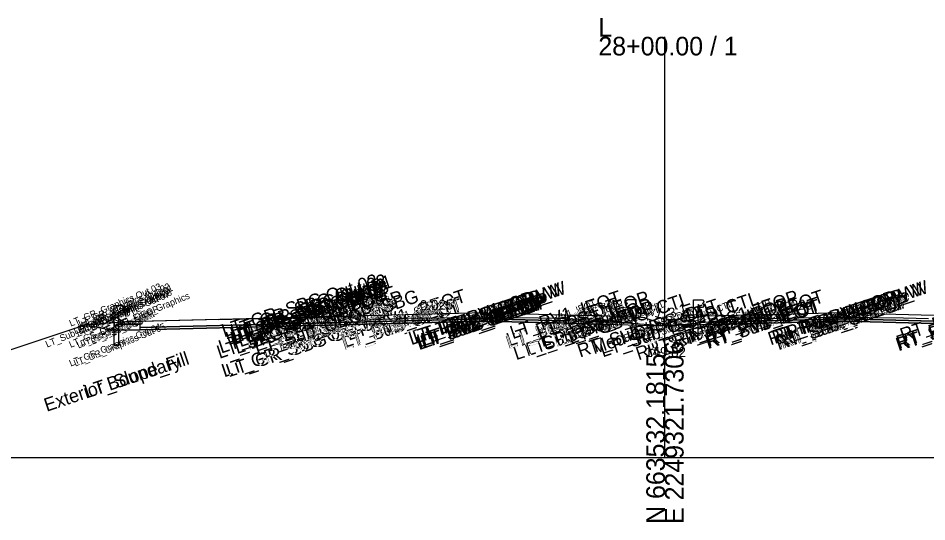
# Model space of a CAD drawing. Extents: x -26 to 2603, y -10 to 9566.
# Drawn here: x 1202.9 to 1339.3, y 7990.3 to 8066 of the extents above; entities that cross this region are included whole.
import ezdxf

# ---------------------------------------------------------------- set-up
doc = ezdxf.new("R2010")
doc.units = 0
for name, color, linetype in [('Exist Cross Section Cell', 7, 'Continuous'), ('Exist XS Center Line Elevation Label', 7, 'Continuous'), ('Exist XS Ground Line', 7, 'Continuous'), ('Matchline', 7, 'Continuous'), ('Prop CMT Concrete Structures', 7, 'Continuous'), ('Prop CMT Guardrail Graphics', 7, 'Continuous'), ('Prop CMT Pvmt Course 1', 7, 'Continuous'), ('Prop CMT Pvmt Course 2', 7, 'Continuous'), ('Prop CMT Pvmt Course 3', 7, 'Continuous'), ('Prop CMT Pvmt Course SBG', 7, 'Continuous'), ('Prop CMT Pvmt Surface', 7, 'Continuous'), ('Prop CMT Pvmt Surface Shoulder', 7, 'Continuous'), ('Prop CMT Shld Paved Course 1', 7, 'Continuous'), ('Prop CMT Shld Paved Course 2', 7, 'Continuous'), ('Prop CMT Shld Paved Course 3', 7, 'Continuous'), ('Prop CMT Slope Grass', 7, 'Continuous'), ('Prop CMT Subgrade Earthwork', 7, 'Continuous'), ('Prop XS SE Text', 7, 'Continuous'), ('Prop XS Side Slope Text', 7, 'Continuous'), ('Scratch_Level_9', 7, 'Continuous')]:
    doc.layers.add(name, color=color, linetype=linetype)

msp = doc.modelspace()

# ---------------------------------------------------------------- linework, layer by layer
at = {"layer": 'Exist Cross Section Cell'}
for p, q in [((1300, 8000), (1300, 8063.21)), ((1000, 8000), (1300, 8000)), ((1300, 8000), (1600, 8000))]:
    msp.add_line(p, q, dxfattribs=at)
at = {"layer": 'Exist XS Ground Line'}
for p, q in [((1261.36, 8020.9), (1272.58, 8021.03)), ((1272.58, 8021.03), (1281.01, 8020.95)), ((1281.01, 8020.95), (1283.78, 8020.91)), ((1314.57, 8020.89), (1325.58, 8021.07)), ((1325.58, 8021.07), (1335.79, 8020.96)), ((1335.79, 8020.96), (1337.73, 8020.94)), ((1337.73, 8020.94), (1339.59, 8020.85)), ((1254.47, 8020.61), (1254.61, 8020.62)), ((1254.61, 8020.62), (1257.59, 8020.75)), ((1257.59, 8020.75), (1259.01, 8020.81)), ((1259.01, 8020.81), (1260.76, 8020.9)), ((1260.76, 8020.9), (1261.36, 8020.9)), ((1283.78, 8020.91), (1284.6, 8020.87)), ((1284.6, 8020.87), (1286.97, 8020.77)), ((1286.97, 8020.77), (1290.29, 8020.53)), ((1290.29, 8020.53), (1298.19, 8019.93)), ((1298.19, 8019.93), (1300, 8019.82)), ((1300, 8019.82), (1300.63, 8019.78)), ((1300.63, 8019.78), (1309.9, 8020.7)), ((1309.9, 8020.7), (1311.47, 8020.83)), ((1311.47, 8020.83), (1314.57, 8020.89))]:
    msp.add_line(p, q, dxfattribs=at)
for points in [[(1233, 8020.72), (1245, 8021.02)], [(1245, 8021.02), (1251, 8021.17)], [(1251, 8021.17), (1253, 8021.1)], [(1253, 8021.1), (1254.47, 8020.61)], [(1213.05, 8019.9), (1157.74, 8001.46)], [(1216.05, 8020.14), (1213.05, 8019.9)], [(1219, 8020.37), (1216.05, 8020.14)], [(1221, 8020.42), (1219, 8020.37)], [(1233, 8020.72), (1221, 8020.42)]]:
    msp.add_lwpolyline(points, dxfattribs=at)
at = {"layer": 'Matchline'}
msp.add_lwpolyline([(1221.24, 8020.43), (1218.91, 8020.33), (1218.24, 8020.68)], dxfattribs=at)
msp.add_lwpolyline([(1221.24, 8020.43), (1218.91, 8020.33), (1218.24, 8020.68)], dxfattribs=at)
at = {"layer": 'Prop CMT Concrete Structures'}
for points in [[(1221.24, 8020.43), (1218.91, 8020.33), (1218.24, 8020.68)], [(1218.24, 8020.68), (1218.24, 8020.01)], [(1221.24, 8020.43), (1218.91, 8020.33), (1218.24, 8020.68)], [(1218.24, 8020.68), (1218.24, 8020.01)], [(1218.24, 8020.01), (1221.24, 8020.01)], [(1218.24, 8020.01), (1221.24, 8020.01)], [(1221.24, 8020.01), (1221.24, 8020.43)], [(1221.24, 8020.01), (1221.24, 8020.43)], [(1273, 8020.47), (1261, 8020.17)], [(1261, 8020.16), (1273, 8020.46)], [(1261, 8020.17), (1261, 8020.16)], [(1273, 8020.47), (1285, 8020.17)], [(1273, 8020.46), (1273, 8020.47)], [(1285, 8020.16), (1273, 8020.46)], [(1285, 8020.17), (1285, 8020.16)], [(1327, 8020.47), (1315, 8020.17)], [(1315, 8020.16), (1327, 8020.46)], [(1315, 8020.17), (1315, 8020.16)], [(1327, 8020.46), (1327, 8020.47)], [(1327, 8020.47), (1344.2, 8020.04)], [(1344.2, 8020.03), (1327, 8020.46)]]:
    msp.add_lwpolyline(points, dxfattribs=at)
at = {"layer": 'Prop CMT Guardrail Graphics'}
for points in [[(1295.7, 8023.69), (1294.37, 8023.69), (1294.1, 8023.4)], [(1295.7, 8023.69), (1294.37, 8023.69), (1294.1, 8023.4)], [(1295.7, 8017.69), (1295.7, 8023.69)], [(1304.3, 8023.69), (1305.63, 8023.69), (1305.9, 8023.4)], [(1304.3, 8023.69), (1305.63, 8023.69), (1305.9, 8023.4)], [(1304.3, 8017.69), (1304.3, 8023.69)], [(1294.1, 8023.4), (1294.37, 8023.11)], [(1294.1, 8023.4), (1294.37, 8023.11)], [(1294.37, 8023.11), (1294.1, 8022.82)], [(1294.37, 8023.11), (1294.1, 8022.82)], [(1294.1, 8022.82), (1294.37, 8022.53), (1295.04, 8022.53)], [(1294.1, 8022.82), (1294.37, 8022.53), (1295.04, 8022.53)], [(1295.04, 8022.53), (1295.04, 8017.69)], [(1305.9, 8022.82), (1305.63, 8022.53), (1304.96, 8022.53)], [(1305.9, 8022.82), (1305.63, 8022.53), (1304.96, 8022.53)], [(1304.96, 8022.53), (1304.96, 8017.69)], [(1305.9, 8023.4), (1305.63, 8023.11)], [(1305.9, 8023.4), (1305.63, 8023.11)], [(1305.63, 8023.11), (1305.9, 8022.82)], [(1305.63, 8023.11), (1305.9, 8022.82)], [(1261, 8020.17), (1221.24, 8019.18)], [(1221.24, 8019.17), (1261, 8020.16)], [(1261, 8020.16), (1261, 8020.17)], [(1285, 8020.17), (1285, 8020.16)], [(1290.79, 8020.02), (1290.78, 8020.03), (1290.28, 8020.04), (1285, 8020.17)], [(1285, 8020.16), (1290.79, 8020.02)], [(1309.21, 8020.02), (1309.22, 8020.03), (1309.72, 8020.04), (1315, 8020.17)], [(1315, 8020.16), (1309.21, 8020.02)], [(1315, 8020.17), (1315, 8020.16)]]:
    msp.add_lwpolyline(points, dxfattribs=at)
at = {"layer": 'Prop CMT Pvmt Course 1'}
for points in [[(1273, 8021.72), (1261, 8021.42)], [(1327, 8021.72), (1344.2, 8021.29)]]:
    msp.add_lwpolyline(points, dxfattribs=at)
at = {"layer": 'Prop CMT Pvmt Course 2'}
for p, q in [((1217.47, 8021.07), (1215.91, 8020.09)), ((1218.24, 8020.68), (1217.47, 8021.07)), ((1297, 8020.96), (1294, 8021.2)), ((1297, 8020.96), (1300, 8019.97)), ((1303, 8020.96), (1300, 8019.97)), ((1303, 8020.96), (1306, 8021.2)), ((1215.91, 8020.09), (1213.05, 8019.9))]:
    msp.add_line(p, q, dxfattribs=at)
msp.add_lwpolyline([(1218.24, 8020.68), (1217.47, 8021.07), (1215.96, 8020.13)], dxfattribs=at)
at = {"layer": 'Prop CMT Pvmt Course 3'}
for points in [[(1217.31, 8016.83), (1217.31, 8022.83)], [(1217.31, 8022.83), (1218.64, 8022.83), (1218.91, 8022.54)], [(1217.31, 8016.83), (1217.31, 8022.83)], [(1217.31, 8022.83), (1218.64, 8022.83), (1218.91, 8022.54)], [(1218.91, 8022.54), (1218.64, 8022.25)], [(1218.91, 8022.54), (1218.64, 8022.25)], [(1218.91, 8021.96), (1218.64, 8021.67), (1217.97, 8021.67)], [(1218.91, 8021.96), (1218.64, 8021.67), (1217.97, 8021.67)], [(1217.97, 8021.67), (1217.97, 8016.83)], [(1217.97, 8021.67), (1217.97, 8016.83)], [(1218.64, 8022.25), (1218.91, 8021.96)], [(1218.64, 8022.25), (1218.91, 8021.96)], [(1217.97, 8016.83), (1217.31, 8016.83)], [(1217.97, 8016.83), (1217.31, 8016.83)]]:
    msp.add_lwpolyline(points, dxfattribs=at)
at = {"layer": 'Prop CMT Pvmt Course SBG'}
for points in [[(1221.24, 8020.01), (1218.24, 8020.01), (1217.74, 8020.01), (1216.91, 8019.18)], [(1221.24, 8020.01), (1218.24, 8020.01), (1217.74, 8020.01), (1217.49, 8019.76)], [(1221.24, 8019.76), (1221.24, 8020.01)], [(1221.24, 8019.18), (1221.24, 8020.01)], [(1216.91, 8019.18), (1221.24, 8019.18)]]:
    msp.add_lwpolyline(points, dxfattribs=at)
at = {"layer": 'Prop CMT Pvmt Surface'}
for points in [[(1273, 8021.72), (1261, 8021.42)], [(1273, 8021.72), (1285, 8021.42)], [(1327, 8021.72), (1315, 8021.42)], [(1327, 8021.72), (1344.2, 8021.29)]]:
    msp.add_lwpolyline(points, dxfattribs=at)
at = {"layer": 'Prop CMT Pvmt Surface Shoulder'}
for points in [[(1273, 8021.72), (1261, 8021.42)], [(1261, 8021.42), (1261, 8020.5)], [(1273, 8021.72), (1285, 8021.42)], [(1273, 8021.6), (1273, 8021.72)], [(1273, 8020.8), (1273, 8021.6), (1273, 8021.6)], [(1285, 8021.42), (1285, 8020.5)], [(1327, 8021.72), (1315, 8021.42)], [(1315, 8021.42), (1315, 8020.5)], [(1327, 8021.6), (1327, 8021.72)], [(1327, 8021.72), (1344.2, 8021.29)], [(1327, 8020.8), (1327, 8021.6), (1327, 8021.6)], [(1261, 8020.5), (1273, 8020.8)], [(1285, 8020.5), (1273, 8020.8)], [(1315, 8020.5), (1327, 8020.8)], [(1344.2, 8020.37), (1327, 8020.8)]]:
    msp.add_lwpolyline(points, dxfattribs=at)
at = {"layer": 'Prop CMT Shld Paved Course 1'}
for points in [[(1261, 8021.42), (1221.24, 8020.43)], [(1261, 8020.5), (1261, 8021.42)], [(1285, 8020.5), (1285, 8021.42)], [(1289, 8021.32), (1294, 8021.2), (1294.94, 8020.26)], [(1311, 8021.32), (1306, 8021.2), (1305.06, 8020.26)], [(1315, 8020.5), (1315, 8021.42)], [(1221.24, 8019.51), (1261, 8020.5)], [(1289.94, 8020.38), (1285, 8020.5)], [(1310.06, 8020.38), (1315, 8020.5)]]:
    msp.add_lwpolyline(points, dxfattribs=at)
at = {"layer": 'Prop CMT Shld Paved Course 2'}
for points in [[(1261, 8020.5), (1221.24, 8019.51)], [(1221.24, 8019.18), (1261, 8020.17)], [(1261, 8020.17), (1261, 8020.5)], [(1285, 8020.17), (1285, 8020.5)], [(1290.28, 8020.04), (1285, 8020.17)], [(1289, 8020.4), (1294.94, 8020.26), (1295.28, 8019.91)], [(1311, 8020.4), (1305.06, 8020.26), (1304.72, 8019.91)], [(1309.72, 8020.04), (1315, 8020.17)], [(1315, 8020.17), (1315, 8020.5)]]:
    msp.add_lwpolyline(points, dxfattribs=at)
at = {"layer": 'Prop CMT Shld Paved Course 3'}
for q in [(1213.05, 8019.9), (1221.24, 8019.17)]:
    msp.add_line((1216.42, 8019.16), q, dxfattribs=at)
for points in [[(1261, 8020.16), (1221.24, 8019.17)], [(1261, 8020.16), (1221.24, 8019.17)], [(1273, 8020.46), (1261, 8020.16)], [(1273, 8020.46), (1261, 8020.16)], [(1273, 8020.46), (1285, 8020.16)], [(1273, 8020.46), (1285, 8020.16)], [(1285, 8020.16), (1290.79, 8020.02)], [(1285, 8020.16), (1290.79, 8020.02)], [(1290.79, 8020.02), (1300, 8019.79)], [(1309.21, 8020.02), (1300, 8019.79)], [(1315, 8020.16), (1309.21, 8020.02)], [(1315, 8020.16), (1309.21, 8020.02)], [(1327, 8020.46), (1315, 8020.16)], [(1327, 8020.46), (1315, 8020.16)], [(1327, 8020.46), (1344.2, 8020.03)], [(1327, 8020.46), (1344.2, 8020.03)]]:
    msp.add_lwpolyline(points, dxfattribs=at)
at = {"layer": 'Prop CMT Slope Grass'}
for points in [[(1273, 8020.8), (1261, 8020.5)], [(1261, 8020.5), (1261, 8020.17)], [(1261, 8020.17), (1273, 8020.47)], [(1273, 8020.47), (1273, 8020.8)], [(1273, 8020.8), (1285, 8020.5)], [(1285, 8020.17), (1273, 8020.47)], [(1285, 8020.5), (1285, 8020.17)], [(1327, 8020.8), (1315, 8020.5)], [(1315, 8020.5), (1315, 8020.17)], [(1315, 8020.17), (1327, 8020.47)], [(1327, 8020.47), (1327, 8020.8)], [(1327, 8020.8), (1344.2, 8020.37)], [(1344.2, 8020.04), (1327, 8020.47)]]:
    msp.add_lwpolyline(points, dxfattribs=at)
at = {"layer": 'Prop CMT Subgrade Earthwork'}
for points in [[(1261, 8021.42), (1221.24, 8020.43)], [(1285, 8021.42), (1289, 8021.32)], [(1289, 8021.32), (1294, 8021.2)], [(1311, 8021.32), (1306, 8021.2)], [(1315, 8021.42), (1311, 8021.32)]]:
    msp.add_lwpolyline(points, dxfattribs=at)

# ---------------------------------------------------------------- texts
at = {"layer": 'Exist Cross Section Cell'}
for s, p in [('L', (1290, 8063.21)), ('28+00.00 / 1', (1290, 8060.41))]:
    msp.add_text(s, height=2.8, dxfattribs=at).set_placement(p)
for s, p in [('E 2249321.7306', (1302.8, 7990)), ('N 663532.1815', (1300, 7990))]:
    msp.add_text(s, height=2.8, rotation=90, dxfattribs=at).set_placement(p)
at = {"layer": 'Exist XS Center Line Elevation Label'}
msp.add_text('149.82', height=1.5, dxfattribs=at).set_placement((1297.02, 8015.07))
at = {"layer": 'Prop XS SE Text'}
for rotation, p in [(1.4321, (1263.23, 8022.11)), (358.5679, (1276.23, 8022.18)), (1.4321, (1317.23, 8022.11)), (358.5679, (1330.23, 8022.18))]:
    msp.add_text('0.025', height=1.5, rotation=rotation, dxfattribs=at).set_placement(p)
at = {"layer": 'Prop XS Side Slope Text'}
for rotation, p in [(341.5651, (1296.77, 8021.69)), (18.4349, (1300.82, 8020.87))]:
    msp.add_text('3:1', height=1.5, rotation=rotation, dxfattribs=at).set_placement(p)
at = {"layer": 'Scratch_Level_9'}
for s, height, rotation, p in [('LT_GR_SBG Out 03', 2, 18.4332, (1233.84, 8018.01)), ('LT_GR_SBG Out 06', 2, 18.4332, (1234.46, 8016.83)), ('LT_GR_SBG Out 02', 2, 18.4332, (1235.17, 8018.01)), ('LT_GR_SBG Out 09', 2, 18.4332, (1235.17, 8017.42)), ('LT_GR_SBG Out 07', 2, 18.4332, (1235.17, 8016.84)), ('LT_GR_SBG Out 08', 2, 18.4332, (1235.44, 8017.13)), ('LT_GR_SBG Out 01', 2, 18.4332, (1235.98, 8017.89)), ('LT_PV1_OEEOP_W', 2, 18.4332, (1261.92, 8016.85)), ('RT_PV1_OEEOP_W', 2, 18.4332, (1315.87, 8016.83)), ('RT_PV1_IEEOP_W', 2, 18.4332, (1316.48, 8017.04)), ('LT_GR_Graphics Out 03', 1, 22.5575, (1210.82, 8019.64)), ('LT_GR_Graphics Out 06', 1, 22.5575, (1211.48, 8018.47)), ('LT_GR_Graphics Out 07', 1, 22.5575, (1212.13, 8018.46)), ('LT_GR_Graphics Out 09', 1, 22.5575, (1212.15, 8019.05)), ('LT_GR_Graphics Out 02', 1, 22.5575, (1212.17, 8019.65)), ('LT_GR_Graphics Out 08', 1, 22.5575, (1212.42, 8018.76)), ('LT_GR_Graphics Out 01', 1, 22.5575, (1212.58, 8019.41)), ('LT_SBG_C1 Shelf Out', 2, 18.4332, (1233.12, 8014.8)), ('LT_CG_Top_BOC', 2, 18.4332, (1237.55, 8016.78)), ('LT_GS_OS_SBG', 2, 18.4332, (1237.8, 8017.51)), ('LT_Sub_OEOP_SBG', 2, 18.4332, (1238.82, 8015.28)), ('LT_PS1_OEOP', 2, 18.4332, (1242.94, 8017.32)), ('LT_PV1_OEOT', 2, 18.4332, (1252.53, 8017.54)), ('LT_PV1_IEEOP_W', 2, 18.4332, (1262.53, 8017.05)), ('LT_PV1_CP_W', 2, 18.4332, (1264.58, 8017.73)), ('LT_PV1_IEOT', 2, 18.4332, (1277.14, 8017.75)), ('RT_PS1_IEOP', 2, 18.4332, (1303.16, 8017.65)), ('RT_PV1_IEOT', 2, 18.4332, (1307.1, 8017.73)), ('RT_PV1_CP_W', 2, 18.4332, (1318.53, 8017.72)), ('RT_PV1_CP', 2, 18.4332, (1320.32, 8018.44)), ('RT_PV1_OEOT', 2, 18.4332, (1335.69, 8017.4)), ('LT_GS_OS_GR_Face_Graphics', 1, 22.5575, (1210.78, 8016.45)), ('LT_Sub_OSS_DLT', 2, 18.4332, (1233.38, 8015.58)), ('LT_Sub_SBG Out', 2, 18.4332, (1235.76, 8015.51)), ('LT_GS_OS_CTL', 2, 18.4332, (1236.25, 8016.54)), ('LT_CG_Bot_BOC', 2, 18.4332, (1237.58, 8016.12)), ('LT_CG_Top_Gut', 2, 18.4332, (1238.18, 8016.42)), ('LT_CG_Bot_IE', 2, 18.4332, (1242.1, 8016.63)), ('LT_PS2_OEOP', 2, 18.4332, (1242.41, 8016.23)), ('LT_Sub_OEOT', 2, 18.4332, (1251.9, 8016.08)), ('LT_PV2_OEOT', 2, 18.4332, (1251.99, 8016.45)), ('LT_PV3_OEOT', 2, 18.4332, (1251.99, 8016.12)), ('LT_PV1_OEOT', 1, 22.5575, (1257.37, 8019.37)), ('LT_Sub_OEEOP', 2, 18.4332, (1263.08, 8016.1)), ('LT_PV2_OEEOP', 2, 18.4332, (1263.17, 8016.47)), ('LT_PV3_OEEOP', 2, 18.4332, (1263.17, 8016.14)), ('LT_Sub_IEEOP', 2, 18.4332, (1263.69, 8016.31)), ('LT_PV2_IEEOP', 2, 18.4332, (1263.78, 8016.68)), ('LT_PV3_IEEOP', 2, 18.4332, (1263.78, 8016.35)), ('LT_PV1_CP', 2, 18.4332, (1266.37, 8018.46)), ('LT_PV1_OEEOP_W', 1, 22.5575, (1268.16, 8019.05)), ('LT_PV1_IEEOP_W', 1, 22.5575, (1268.51, 8019.19)), ('LT_PV1_CP_W', 1, 22.5575, (1269.42, 8019.57)), ('LT_PV1_CP', 1, 22.5575, (1270.3, 8020.06)), ('LT_PV2_IEOT', 2, 18.4332, (1276.61, 8016.65)), ('LT_PV3_IEOT', 2, 18.4332, (1276.61, 8016.32)), ('LT_PS1_IEOP', 2, 18.4332, (1281.2, 8017.67)), ('LT_PS2_IEOP', 2, 18.4332, (1281.61, 8016.55)), ('LT_PV1_IEOT', 1, 22.5575, (1281.72, 8019.52)), ('LT_GS_IS_CTL', 2, 18.4332, (1285.84, 8016.98)), ('RT_Sub_ISS_DLT', 2, 18.4332, (1287.25, 8015)), ('LT_Sub_ISS_DLT', 2, 18.4332, (1290.66, 8015.02)), ('RT_GS_IS_CTL', 2, 18.4332, (1295.8, 8016.96)), ('RT_PS2_IEOP', 2, 18.4332, (1301.68, 8016.53)), ('RT_Sub_IEOT', 2, 18.4332, (1306.47, 8016.27)), ('RT_PV2_IEOT', 2, 18.4332, (1306.56, 8016.64)), ('RT_PV3_IEOT', 2, 18.4332, (1306.56, 8016.31)), ('RT_PS1_IEOP', 1, 22.5575, (1307.71, 8019.41)), ('RT_PV1_IEOT', 1, 22.5575, (1311.67, 8019.5)), ('RT_Sub_OEEOP', 2, 18.4332, (1317.04, 8016.09)), ('RT_PV2_OEEOP', 2, 18.4332, (1317.13, 8016.46)), ('RT_PV3_OEEOP', 2, 18.4332, (1317.13, 8016.13)), ('RT_Sub_IEEOP', 2, 18.4332, (1317.65, 8016.29)), ('RT_PV2_IEEOP', 2, 18.4332, (1317.74, 8016.66)), ('RT_PV3_IEEOP', 2, 18.4332, (1317.74, 8016.33)), ('RT_PV1_OEEOP_W', 1, 22.5575, (1322.11, 8019.02)), ('RT_PV1_IEEOP_W', 1, 22.5575, (1322.46, 8019.17)), ('RT_PV1_CP_W', 1, 22.5575, (1323.36, 8019.54)), ('RT_PV1_CP', 1, 22.5575, (1324.25, 8020.04)), ('RT_Sub_OEOT', 2, 18.4332, (1335.06, 8015.93)), ('RT_PV2_OEOT', 2, 18.4332, (1335.15, 8016.3)), ('RT_PV3_OEOT', 2, 18.4332, (1335.15, 8015.97)), ('LT_GS_OS_CTL', 1, 22.5575, (1211.9, 8018.09)), ('LT_PS1_OEOP', 1, 22.5575, (1215.41, 8018.34)), ('LT_Sub_OEOP', 2, 18.4332, (1242.29, 8015.84)), ('LT_PS3_OEOP', 2, 18.4332, (1242.41, 8015.89)), ('LT_PV2_OEOT', 1, 22.5575, (1257.26, 8018.41)), ('LT_PV3_OEOT', 1, 22.5575, (1257.26, 8018.08)), ('LT_Sub_OEOT', 1, 22.5575, (1257.28, 8018.08)), ('LT_PV2_OEEOP', 1, 22.5575, (1268.94, 8018.58)), ('LT_PV3_OEEOP', 1, 22.5575, (1268.94, 8018.24)), ('LT_Sub_OEEOP', 1, 22.5575, (1268.96, 8018.24)), ('LT_PV2_IEEOP', 1, 22.5575, (1269.29, 8018.72)), ('LT_PV3_IEEOP', 1, 22.5575, (1269.29, 8018.39)), ('LT_Sub_IEEOP', 1, 22.5575, (1269.31, 8018.39)), ('LT_Sub_IEOT', 2, 18.4332, (1276.52, 8016.28)), ('LT_Sub_Trench_In', 2, 18.4332, (1277.66, 8014.59)), ('LT_PS3_Shelf_In', 2, 18.4332, (1279.34, 8015.16)), ('LT_PV2_IEOT', 1, 22.5575, (1281.61, 8018.56)), ('LT_PV3_IEOT', 1, 22.5575, (1281.61, 8018.22)), ('LT_Sub_IEOT', 1, 22.5575, (1281.64, 8018.22)), ('LT_PS3_IEOP', 2, 18.4332, (1281.95, 8016.21)), ('LT_PS1_IEOP', 1, 22.5575, (1285.76, 8019.44)), ('LT_Sub_Trench_In', 1, 22.5575, (1286.11, 8017.53)), ('LT_PS2_IEOP', 1, 22.5575, (1286.59, 8018.45)), ('LT_PS3_Shelf_In', 1, 22.5575, (1286.6, 8017.75)), ('LT_PS3_IEOP', 1, 22.5575, (1286.93, 8018.11)), ('Med_Ditch_CTL', 2, 18.4332, (1289.34, 8015.47)), ('LT_GS_IS_CTL', 1, 22.5575, (1291.35, 8019.03)), ('RT_Sub_ISS_DLT', 1, 22.5575, (1294.05, 8017.43)), ('RT_Sub_Trench_In', 2, 18.4332, (1296.03, 8014.57)), ('Med_Ditch_CTL', 1, 22.5575, (1295.94, 8017.85)), ('LT_Sub_ISS_DLT', 1, 22.5575, (1297.47, 8017.45)), ('RT_PS3_Shelf_In', 2, 18.4332, (1297.73, 8015.14)), ('RT_PS3_IEOP', 2, 18.4332, (1301.34, 8016.19)), ('RT_GS_IS_CTL', 1, 22.5575, (1301.3, 8019)), ('RT_Sub_Trench_In', 1, 22.5575, (1304.47, 8017.51)), ('RT_PS3_Shelf_In', 1, 22.5575, (1304.99, 8017.73)), ('RT_PS3_IEOP', 1, 22.5575, (1306.32, 8018.08)), ('RT_PS2_IEOP', 1, 22.5575, (1306.66, 8018.43)), ('RT_PV2_IEOT', 1, 22.5575, (1311.56, 8018.53)), ('RT_PV3_IEOT', 1, 22.5575, (1311.56, 8018.2)), ('RT_Sub_IEOT', 1, 22.5575, (1311.58, 8018.2)), ('RT_PV2_OEEOP', 1, 22.5575, (1322.88, 8018.55)), ('RT_PV3_OEEOP', 1, 22.5575, (1322.88, 8018.22)), ('RT_Sub_OEEOP', 1, 22.5575, (1322.9, 8018.22)), ('RT_PV2_IEEOP', 1, 22.5575, (1323.23, 8018.7)), ('RT_PV3_IEEOP', 1, 22.5575, (1323.23, 8018.37)), ('RT_Sub_IEEOP', 1, 22.5575, (1323.26, 8018.36)), ('LT_Sub_OSS_DLT', 1, 22.5575, (1207.25, 8016.49)), ('LT_Sub_Trench_Out', 1, 22.5575, (1211.96, 8016.35)), ('LT_PS3_Shelf_Out', 1, 22.5575, (1212.48, 8016.57)), ('LT_PS3_OEOP', 1, 22.5575, (1214.02, 8017.01)), ('LT_PS2_OEOP', 1, 22.5575, (1214.36, 8017.35)), ('LT_GR_SBG Out 04', 2, 18.4332, (1233.84, 8012.01)), ('LT_GR_SBG Out 05', 2, 18.4332, (1234.5, 8012.01)), ('LT_GR_Graphics Out 04', 1, 22.5575, (1210.81, 8013.63)), ('LT_GR_Graphics Out 05', 1, 22.5575, (1211.49, 8013.64)), ('LT_Slope_Fill', 2, 18.4332, (1213.23, 8008.86)), ('LT_Slope_Fill', 2, 18.4332, (1213.23, 8008.86)), ('Exterior Boundary', 2, 18.4332, (1207.18, 8006.85)), ('Exterior Boundary', 2, 18.4332, (1207.18, 8006.85))]:
    msp.add_text(s, height=height, rotation=rotation, dxfattribs=at).set_placement(p)

doc.saveas('drawing.dxf')
